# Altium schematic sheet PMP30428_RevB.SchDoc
size 431 x 279 mm; Date: Not shown in title block; ApprovedBy: Not shown in title block; CheckedBy: Not shown in title block; Author: Not shown in title block; CompanyName: Not shown in title block; Engineer: Not shown in title block; Organization: Not shown in title block; Address1: Not shown in title block; Address2: Not shown in title block; Address3: Not shown in title block; Address4: Not shown in title block; DocumentNumber: 1; Revision: Use project parameter SCH_Rev; SheetNumber: 1; SheetTotal: 1; PageSetup: Record=PageOptions¦CenterHorizontal=True¦CenterVertical=True¦PrintScale=1.00¦XCorrection=1.00¦YCorrection=1.00¦PrintKind=0¦BorderSize=5000000¦LeftOffset=0¦BottomOffset=0¦Orientation=2¦PaperLength=1000¦PaperWidth=1000¦Scale=100¦PaperSource=15¦PrintQuality=600¦MediaType=1¦DitherType=10¦PaperKind=Letter¦PrintScaleMode=1
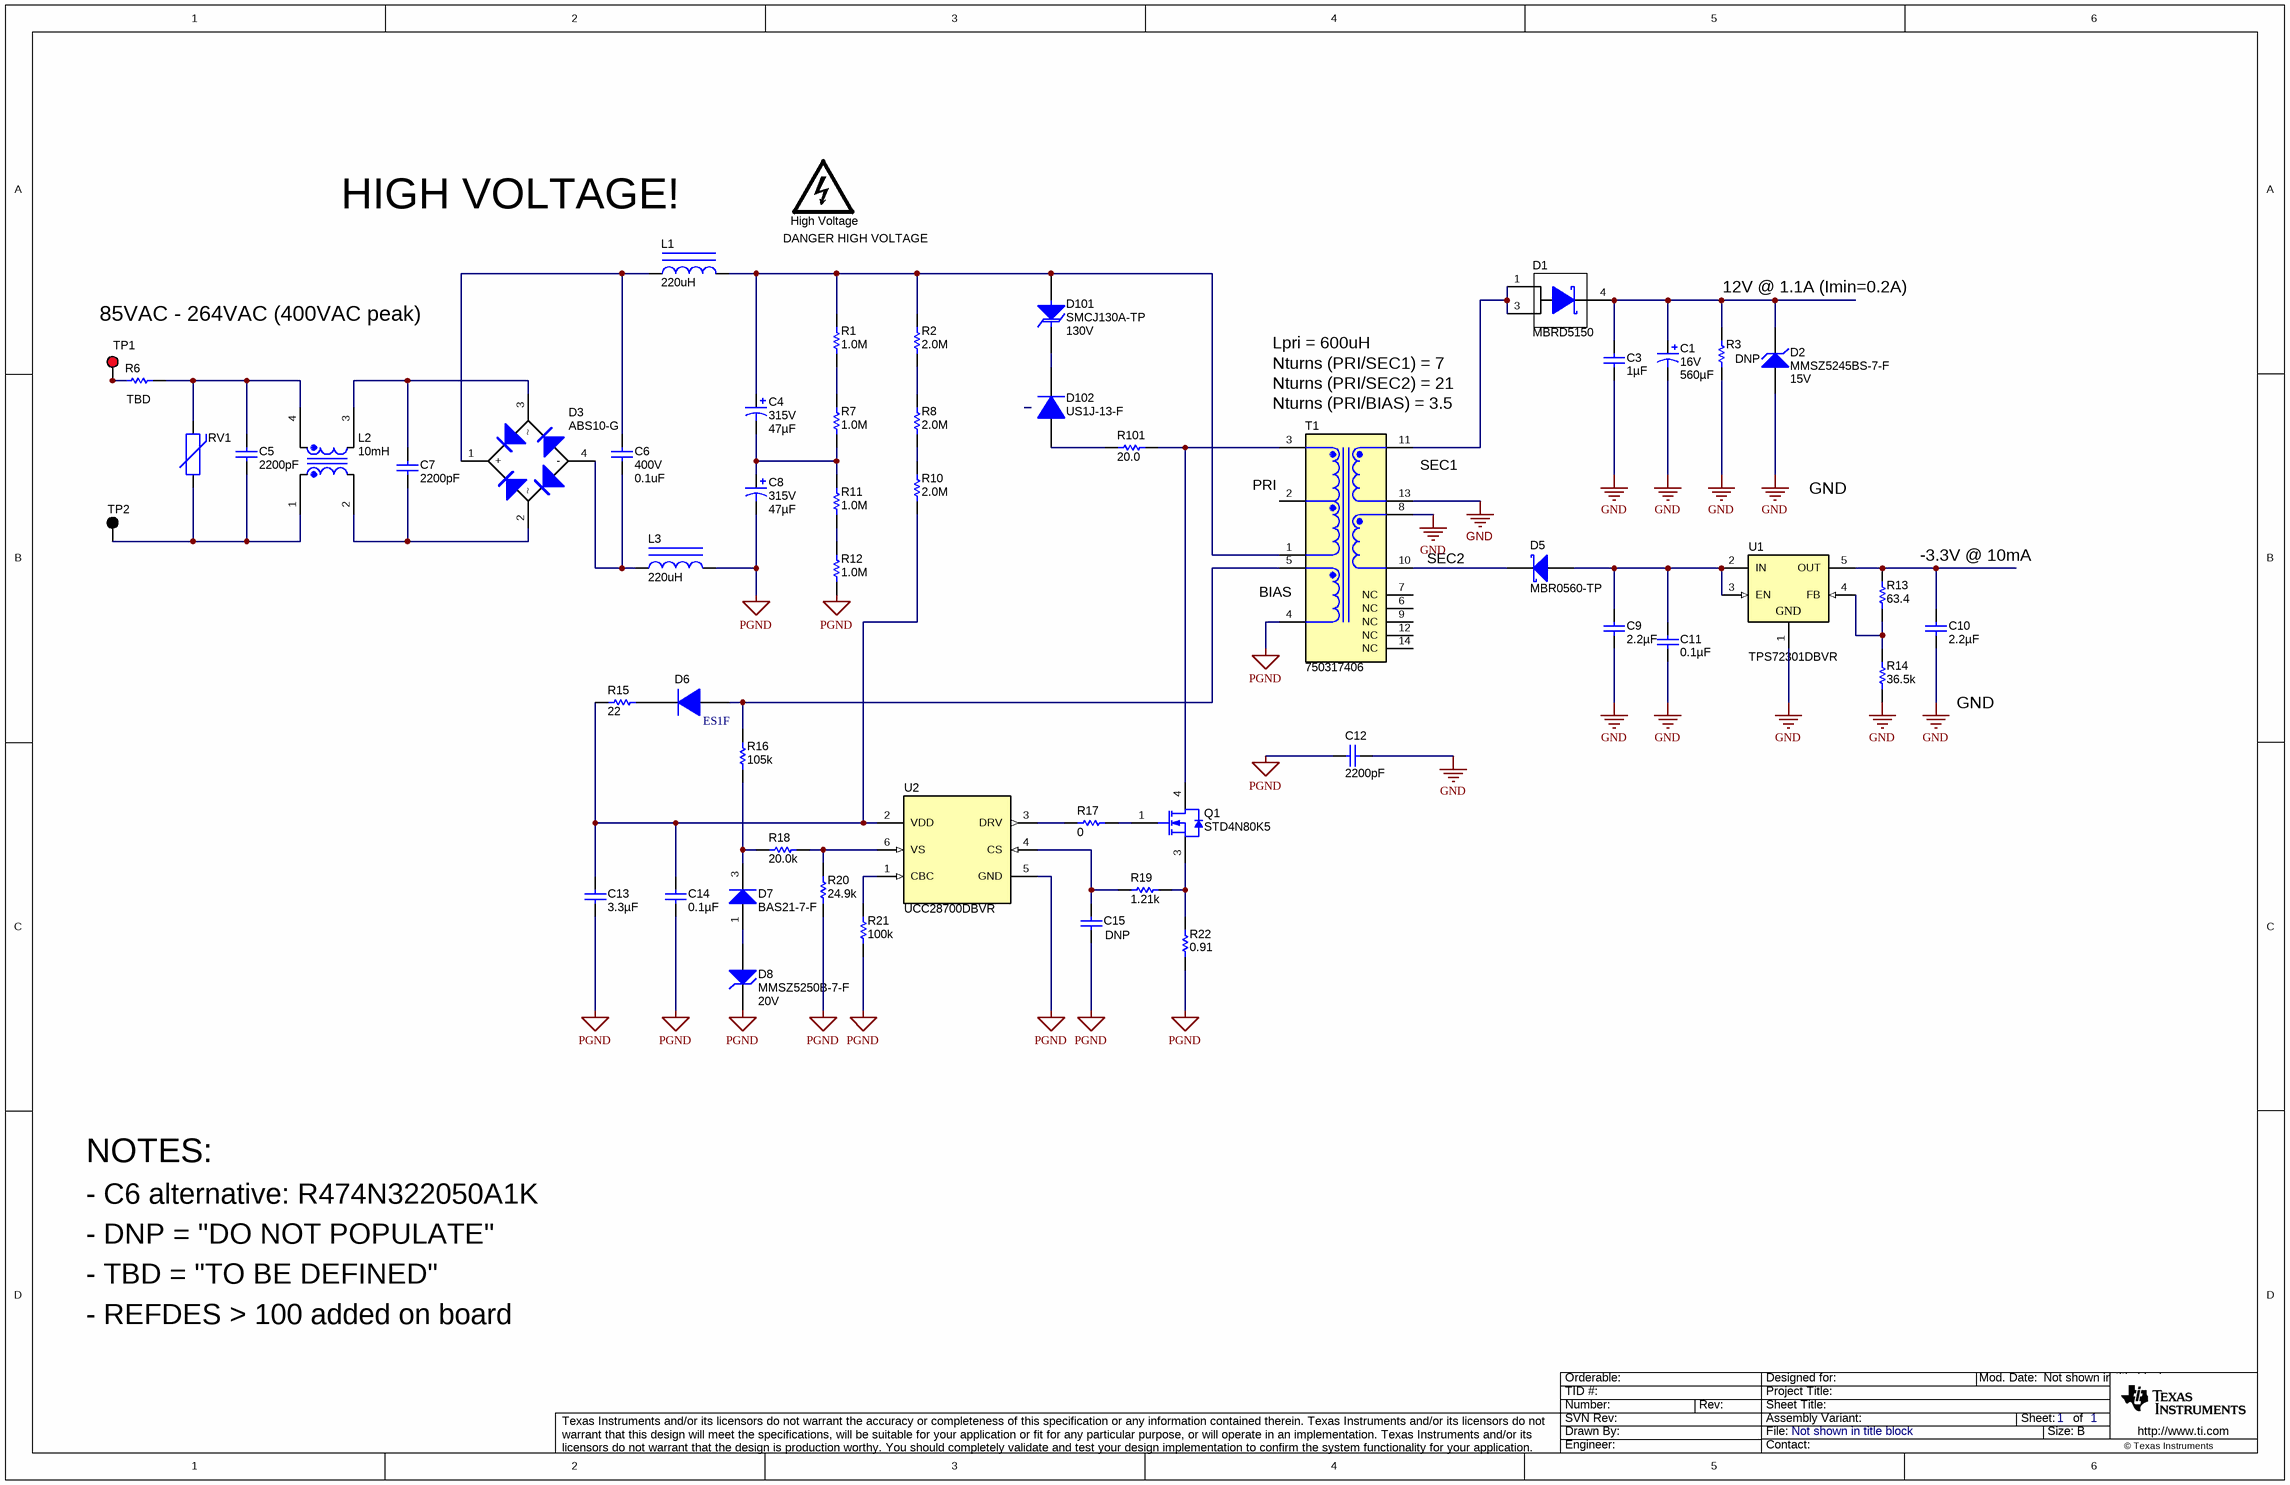
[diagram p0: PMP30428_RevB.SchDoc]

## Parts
C1  VDC_V: 16V  ValueDisplayed: 560µF  [Panasonic_SMT_800x1190]  (hidden comment: 16SVF560M)
C3  ValueDisplayed: 1µF  [0805_HV]  (hidden comment: C0805C105K4RACTU)
C4  VDC_V: 315V  ValueDisplayed: 47µF  [VZ_1600x2500]  (hidden comment: UVZ2F470MHD)
C5  ValueDisplayed: 2200pF  [VY2_900x500_5]  (hidden comment: VY2222M35Y5UG6TV5)
C6  VDC_V: 400V  ValueDisplayed: 0.1uF  [ECQE_F_1200x630x1200]  (hidden comment: ECQ-E4104JF)
C7  ValueDisplayed: 2200pF  [VY2_900x500_5]  (hidden comment: VY2222M35Y5UG6TV5)
C8  VDC_V: 315V  ValueDisplayed: 47µF  [VZ_1600x2500]  (hidden comment: UVZ2F470MHD)
C9  ValueDisplayed: 2.2µF  [0805_HV]  (hidden comment: C0805C225K8RACTU)
C10  ValueDisplayed: 2.2µF  [0805_HV]  (hidden comment: C0805C225K8RACTU)
C11  ValueDisplayed: 0.1µF  [0805_HV]  (hidden comment: GRM219R71C104KA01D)
C12  ValueDisplayed: 2200pF  [CD45_900x600x1300]  (hidden comment: CD45-E2GA222M-NKA)
C13  ValueDisplayed: 3.3µF  [1206_190]  (hidden comment: C3216X7R1H335K160AC)
C14  ValueDisplayed: 0.1µF  [0603]  (hidden comment: GRM188R71H104KA93D)
C15  value DNP  [0603]  (hidden comment: Used in BOM report)
D1  MBRD5150  [DPAK]
D2  MMSZ5245BS-7-F  value 15V  [SOD-323]
D3  ABS10-G  [ABS]
D5  MBR0560-TP  [SOD-123]
D6  ES1F  [SMA]
D7  BAS21-7-F  [SOT-23]
D8  MMSZ5250B-7-F  value 20V  [SOD-123]
D101  SMCJ130A-TP  value 130V  [SMC]
D102  US1J-13-F  [SMA]
High_Voltage  DANGER HIGH VOLTAGE  [IEC_HighVoltage_Small]  (no BOM)
L1  ValueDisplayed: 220uH  [WE-TI_5075]  (hidden comment: 7447462221)
L2  value 10mH  [Wurth_WE-TFC_UT]  (hidden comment: 744862100)
L3  ValueDisplayed: 220uH  [WE-TI_5075]  (hidden comment: 7447462221)
Q1  STD4N80K5  [DPAK]
R1  ValueDisplayed: 1.0M  [0805_HV]  (hidden comment: CRCW08051M00JNEA)
R2  ValueDisplayed: 2.0M  [0805_HV]  (hidden comment: CRCW08052M00JNEA)
R3  value DNP  [0805]  (hidden comment: Used in BOM report)
R6  TBD  [1206]
R7  ValueDisplayed: 1.0M  [0805_HV]  (hidden comment: CRCW08051M00JNEA)
R8  ValueDisplayed: 2.0M  [0805_HV]  (hidden comment: CRCW08052M00JNEA)
R10  ValueDisplayed: 2.0M  [0805_HV]  (hidden comment: CRCW08052M00JNEA)
R11  ValueDisplayed: 1.0M  [0805_HV]  (hidden comment: CRCW08051M00JNEA)
R12  ValueDisplayed: 1.0M  [0805_HV]  (hidden comment: CRCW08051M00JNEA)
R13  ValueDisplayed: 63.4  [0603]  (hidden comment: CRCW060363R4FKEA)
R14  ValueDisplayed: 36.5k  [0603]  (hidden comment: CRCW060336K5FKEA)
R15  ValueDisplayed: 22  [0805_HV]  (hidden comment: CRCW080522R0JNEA)
R16  ValueDisplayed: 105k  [0603]  (hidden comment: CRCW0603105KFKEA)
R17  ValueDisplayed: 0  [0805_HV]  (hidden comment: CRCW08050000Z0EA)
R18  ValueDisplayed: 20.0k  [0603]  (hidden comment: CRCW060320K0FKEA)
R19  ValueDisplayed: 1.21k  [0603]  (hidden comment: CRCW06031K21FKEA)
R20  ValueDisplayed: 24.9k  [0603]  (hidden comment: CRCW060324K9FKEA)
R21  ValueDisplayed: 100k  [0603]  (hidden comment: CRCW0603100KFKEA)
R22  ValueDisplayed: 0.91  [0805_HV]  (hidden comment: ERJ-6RQFR91V)
R101  ValueDisplayed: 20.0  [2010]  (hidden comment: CRCW201020R0FKEF)
RV1  B72214S0421K331  [TDK_B72214S0421]  (value not drawn)
T1  750317406  [Wurth_750317406]
TP1  5000  [Keystone5000]  (value not drawn)
TP2  5001  [Keystone5001]  (value not drawn)
U1  TPS72301DBVR  [DBV0005A_N]
U2  UCC28700DBVR  [DBV0006A_N]

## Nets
GND: C1.2(-) C3.2 C9.2 C10.2 C11.2 C12.1 D2.2(A) R3.1 R14.1 T1.8 T1.13 U1.1(GND)
PGND: C8.2(-) C12.2 C13.2 C14.2 C15.2 D8.1(K) L3.2 R12.1 R20.1 R21.1 R22.1 T1.4 U2.5(GND)
NetC1_1: C1.1(+) C3.1 D1.4(K) D2.1(K) R3.2
NetC4_1: C4.1(+) D101.2(A) L1.2 R1.2 R2.2 T1.1
NetC4_2: C4.2(-) C8.1(+) R7.1 R11.2
NetC5_1: C5.1 L2.4 R6.1 RV1.2
NetC5_2: C5.2 L2.1 RV1.1 TP2.1
NetC6_1: C6.1 D3.1(+) L1.1
NetC6_2: C6.2 D3.4(-) L3.1
NetC7_1: C7.1 D3.3 L2.3
NetC7_2: C7.2 D3.2 L2.2
NetC9_1: C9.1 C11.1 D5.2(A) U1.2(IN) U1.3(EN)
NetC10_1: C10.1 R13.2 U1.5(OUT)
NetC13_1: C13.1 C14.1 R10.1 R15.1 U2.2(VDD)
NetC15_1: C15.1 R19.1 U2.4(CS)
NetD1_1: D1.1(A) D1.3(A) T1.11
NetD5_1: D5.1(K) T1.10
NetD6_1: D6.1(K) R15.2
NetD6_2: D6.2(A) R16.2 T1.5
NetD7_1: D7.1(A) D8.2(A)
NetD7_3: D7.3(K) R16.1 R18.1
NetD101_1: D101.1(K) D102.1(K)
NetD102_2: D102.2(A) R101.1
NetQ1_1: Q1.1(G) R17.2
NetQ1_3: Q1.3(S) R19.2 R22.2
NetQ1_4: Q1.4(D) R101.2 T1.3
NetR1_1: R1.1 R7.2
NetR2_1: R2.1 R8.2
NetR6_2: R6.2 TP1.1
NetR8_1: R8.1 R10.2
NetR11_1: R11.1 R12.2
NetR13_1: R13.1 R14.2 U1.4(FB)
NetR17_1: R17.1 U2.3(DRV)
NetR18_2: R18.2 R20.2 U2.6(VS)
NetR21_2: R21.2 U2.1(CBC)

Not connected (* = marked no-connect by the designer): T1 2 6(NC) 7(NC) 9(NC) 12(NC) 14(NC)

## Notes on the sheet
- HIGH VOLTAGE!
- 12V @ 1.1A (Imin=0.2A)
- 85VAC - 264VAC (400VAC peak)
- Lpri = 600uH
- Nturns (PRI/SEC1) = 7
- Nturns (PRI/SEC2) = 21
- (near T1) Nturns (PRI/BIAS) = 3.5
- (near T1) PRI
- (near T1) SEC1
- GND
- (near T1) SEC2
- -3.3V @ 10mA
- (near T1) BIAS
- NOTES:
- - C6 alternative: R474N322050A1K
- - DNP = "DO NOT POPULATE"
- - TBD = "TO BE DEFINED"
- - REFDES > 100 added on board

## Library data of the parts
C1 = CMP-0081113-1: CAP, Aluminum Polymer, 560 µF, 16 V,+/- 20%, 0.014 ohm, 8x11.9 SMD; Manufacturer: Panasonic; TaMin_C: -55°C; ESR_ohm: 0.014; Polarized: Y; SizeAreaWB_mm2: 106.09; Value: 560uF; TaMax_C: 125°C; SizeZ_mm: 12; SizeX_mm: 8.3; Cap_Case: 0.8x11.9mm; SizeArea_mm2: 68.89; CompType: Capacitor; AEC Qualified: N; IRMS_A: 1.56A; AEC Category: Q200
C3 = C0805C105K4RACTU: CAP, CERM, 1 µF, 16 V,+/- 10%, X7R, 0805; Manufacturer: Kemet; Polarized: N; CompType: Capacitor; Value: 1uF; U/M: EA; Cap_F: 0.000001; Tolerance_%: 10; ESR_ohm: 0.015; Value1: 0.015 ohm; VDC_V: 16; Value2: 16V; IRMS_A: 8.19; TaMin_C: -55; TaMax_C: 125; Cap_Case: 0805; SizeArea_mm2: 2.5; SizeAreaWB_mm2: 6.75; SizeX_mm: 2; SizeY_mm: 1.25; SizeZ_mm: 1.45; AEC Category: Q200; Green_Lifecycle: Active; Green_REACh: Passed
C4 C8 = CMP-0081190-1: CAP, AL, 47 µF, 315 V, +/- 20%, TH; Manufacturer: Nichicon; TaMin_C: -40°C; Polarized: Y; SizeAreaWB_mm2: 324; U/M: EA; Value: 47uF; TaMax_C: 105°C; SizeZ_mm: 27; SizeX_mm: 16; Cap_Case: 16x25mm; SizeArea_mm2: 256; CompType: Capacitor; AEC Qualified: N; AEC Category: Q200
C5 = CMP-0080613-1: CAP, CERM, 2200 pF, X1 440 VAC/Y2 300 VAC, +/- 20%, Y5U, Body9x5mm; Manufacturer: Vishay-Bccomponents; TaMin_C: -40°C; Polarized: N; AC_Safety: X1Y2; SizeAreaWB_mm2: 77; U/M: EA; Value: 2200pF; TaMax_C: 125°C; VAC_Y: 300V; VAC_X: 440V; SizeZ_mm: 13; SizeX_mm: 9; SizeY_mm: 5; Cap_Case: 9x5mm; SizeArea_mm2: 45; CompType: Capacitor; Cap_F: 2.2nF; AEC Category: Q200
C6 = CMP-0064980-3: CAP, Film, 0.1 uF, 400 V,+/- 5%, TH; Manufacturer: Panasonic; TaMin_C: -40°C; Polarized: N; SizeAreaWB_mm2: 116.2; Value1: Unknown; Value: 0.1uF; TaMax_C: 105°C; SizeZ_mm: 12; SizeY_mm: 6.3; Cap_Case: 12x6.3x12mm; SizeArea_mm2: 75.6; CompType: Capacitor; Cap_F: 100nF; AEC Category: Q200
C7 = CMP-0080613-1: CAP, CERM, 2200 pF, X1 440 VAC/Y2 300 VAC, +/- 20%, Y5U, Body9x5mm; Manufacturer: Vishay-Bccomponents; TaMin_C: -40°C; Polarized: N; AC_Safety: X1Y2; SizeAreaWB_mm2: 77; U/M: EA; Value: 2200pF; TaMax_C: 125°C; VAC_Y: 300V; VAC_X: 440V; SizeZ_mm: 13; SizeX_mm: 9; SizeY_mm: 5; Cap_Case: 9x5mm; SizeArea_mm2: 45; Cap_F: 2.2nF; AEC Category: Q200
C9 C10 = C0805C225K8RACTU: CAP, CERM, 2.2 µF, 10 V,+/- 10%, X7R, 0805; Manufacturer: Kemet; Polarized: N; CompType: Capacitor; Value: 2.2uF; U/M: EA; Cap_F: 0.0000022; Tolerance_%: 10; ESR_ohm: 0.008; Value1: 0.008 ohm; Value2: 10V; IRMS_A: 15.55; TaMin_C: -55; TaMax_C: 125; Cap_Case: 0805; SizeArea_mm2: 2.5; SizeAreaWB_mm2: 6.75; SizeX_mm: 2; SizeY_mm: 1.25; SizeZ_mm: 1.45; AEC Category: Q200; Green_Lifecycle: Active; Green_REACh: Passed
C11 = GRM219R71C104KA01D: CAP, CERM, 0.1 µF, 16 V,+/- 10%, X7R, 0805; Manufacturer: MuRata; Polarized: N; CompType: Capacitor; Value: 0.1uF; U/M: EA; Cap_F: 0.0000001; Tolerance_%: 10; VDC_V: 16; Value2: 16V; TaMin_C: -55; TaMax_C: 125; Cap_Case: 0805; SizeArea_mm2: 2.5; SizeAreaWB_mm2: 6.75; SizeX_mm: 2; SizeY_mm: 1.25; SizeZ_mm: 1.45; AEC Category: Q200; Green_Lifecycle: Active; Green_REACh: Passed
C12 = CD45-E2GA222M-NKA: CAP, CERM, 2200 pF, X1 440 VAC/Y1 400 VAC, +/- 20%, E, D9xT6mm; Manufacturer: TDK; Polarized: N; CompType: Capacitor; Value: 2200pF; U/M: EA; Cap_F: 0.0000000022; Tolerance_%: 20; TaMin_C: -25; TaMax_C: 125; Cap_Case: 9x6x13mm; SizeArea_mm2: 63.9; SizeAreaWB_mm2: 101.2; SizeX_mm: 10.65; SizeY_mm: 6; SizeZ_mm: 13; AEC Category: Q200; Green_Lifecycle: Not Set; Green_REACh: Incomplete; AC_Safety: X1Y1; VAC_X: 440; VAC_Y: 400
C13 = C3216X7R1H335K160AC: CAP, CERM, 3.3 µF, 50 V,+/- 10%, X7R, 1206; Manufacturer: TDK; Polarized: N; CompType: Capacitor; Value: 3.3uF; U/M: EA; Cap_F: 0.0000033; Tolerance_%: 10; VDC_V: 50; Value2: 50V; TaMin_C: -55; TaMax_C: 125; Cap_Case: 1206; SizeArea_mm2: 5.12; SizeAreaWB_mm2: 10.92; SizeX_mm: 3.2; SizeY_mm: 1.6; SizeZ_mm: 1.9; AEC Category: Q200; Green_Lifecycle: Active; Green_REACh: Passed
C14 = GRM188R71H104KA93D: CAP, CERM, 0.1 µF, 50 V,+/- 10%, X7R, 0603; Manufacturer: MuRata; Polarized: N; CompType: Capacitor; Value: 0.1uF; U/M: EA; Cap_F: 0.0000001; Tolerance_%: 10; VDC_V: 50; Value2: 50V; TaMin_C: -55; TaMax_C: 125; SizeArea_mm2: 1.28; SizeAreaWB_mm2: 4.68; SizeX_mm: 1.6; SizeY_mm: 0.8; SizeZ_mm: 1; AEC Category: Q200; Green_Lifecycle: Active; Green_REACh: Passed
C15 = Capacitor: CAP, CERM, xxxF, xxV, [TempCo], xx%, [PackageReference]; Polarized: N; U/M: EA
D1 = MBRD360T4G: Diode, Schottky, 150V, DPAK; Manufacturer: ON Semiconductor; U/M: EA; Vf_V: 0.6; Value2: 0.6V; Io_A: 3; Vr_V: 60; TJmax_C: 150; RJC_CperW: 6; SizeAreaWB_mm2: 101.7114; SizeArea_mm2: 64.8114; SizeX_mm: 9.91; SizeY_mm: 6.54; SizeZ_mm: 2.29; AEC Category: Q101; Green_Lifecycle: Not Set; Green_REACh: Incomplete; Speed: Fast Recovery =< 500ns, > 200mA (Io); Capacitance @ Vr, F: 150pF @ 5V, 1MHz
D2 = MMSZ5245BS-7-F: Diode, Zener, 15 V, 200 mW, SOD-323; Manufacturer: Diodes Inc.; SymbolCreator: a0412235; U/M: EA; Power_W: 0.2; Vz_V: 15; Value1: 0.2W; RJA_CperW: 350; SizeAreaWB_mm2: 8.695; SizeArea_mm2: 3.645; SizeX_mm: 2.7; SizeY_mm: 1.35; SizeZ_mm: 1; AEC Category: Q101
D3 = ABS10-G: Diode, Switching-Bridge, 1000 V, 1 A, 6.2x5.0mm; Manufacturer: Comchip Technology; U/M: EA; Vf_V: 1.1; Value: 1000V; Value1: 1A; Value2: 1.1V; Io_A: 1; Vr_V: 1000; TJmax_C: 150; RJC_CperW: 12; SizeAreaWB_mm2: 57.4; SizeArea_mm2: 31; SizeX_mm: 6.2; SizeY_mm: 5; SizeZ_mm: 1.5; AEC Category: Q101; AEC Qualified: N
D5 = MBR0560-TP: Diode, Schottky, 60 V, 3 A, SOD-123; Manufacturer: Micro Commercial Components; U/M: EA; Vf_V: 0.45; Value: 60V; Value1: 3A; Value2: 0.45V; Io_A: 3; Vr_V: 60; TJmax_C: 150; SizeAreaWB_mm2: 13.095; SizeArea_mm2: 6.545; SizeX_mm: 3.85; SizeY_mm: 1.7; SizeZ_mm: 1.35; AEC Category: Q101; Green_Lifecycle: Not Set; Green_REACh: Incomplete
D6 = ES1G-13-F: Diode, Superfast Rectifier, 400 V, 1 A, SMA; Manufacturer: Diodes Inc.; U/M: EA; Vf_V: 1.25; Value: 300V; Value1: 1A; Value2: 1.25V; Io_A: 1; Vr_V: 300; TJmax_C: 150; RJC_CperW: 25; SizeAreaWB_mm2: 37.3428; SizeArea_mm2: 16.3228; SizeX_mm: 5.59; SizeY_mm: 2.92; SizeZ_mm: 2.87; AEC Category: Q101; Green_Lifecycle: Active; Green_REACh: Passed; Element Configuration: Single; Forward Voltage: 1.3V; Reverse Recovery Time: 35ns; Peak Non-Repetitive Surge Current: 30A; Peak Reverse Current: 5uA
D7 = BAS21-7-F: Diode, Switching, 200 V, 0.2 A, SOT-23; Manufacturer: Diodes Inc.; U/M: EA; Vf_V: 1.25; Value: 200V; Value1: 0.2A; Value2: 1.25V; Io_A: 0.2; Vr_V: 200; TJmax_C: 150; SizeAreaWB_mm2: 14; SizeArea_mm2: 7.5; SizeX_mm: 2.5; SizeY_mm: 3; SizeZ_mm: 1.1; AEC Category: Q101; Green_Lifecycle: Active; Green_REACh: Passed
D8 = MMSZ5250B-7-F: Diode, Zener, 20 V, 500 mW, SOD-123; Manufacturer: Diodes Inc.; SymbolCreator: a0412235; U/M: EA; Power_W: 0.5; Vz_V: 20; Value1: 0.5W; RJA_CperW: 350; SizeAreaWB_mm2: 13.095; SizeArea_mm2: 6.545; SizeX_mm: 3.85; SizeY_mm: 1.7; SizeZ_mm: 1.35; AEC Category: Q101
D101 = SMCJ120A-TP: Diode, TVS, Uni, 130 V, SMC; Manufacturer: Micro Commercial Components; U/M: EA; Vr_V: 130; Value1: W; SizeAreaWB_mm2: 83.2686; SizeArea_mm2: 50.5686; SizeX_mm: 8.13; SizeY_mm: 6.22; SizeZ_mm: 2.6; AEC Category: Q101; AEC Qualified: N
D102 = US1J-13-F: Diode, Ultrafast, 600 V, 1 A, SMA; Manufacturer: Diodes Inc.; U/M: EA; Vf_V: 1.7; Value: 600V; Value1: 1A; Value2: 1.7V; Io_A: 1; Vr_V: 600; TJmax_C: 150; SizeAreaWB_mm2: 37.3428; SizeArea_mm2: 16.3228; SizeX_mm: 5.59; SizeY_mm: 2.92; SizeZ_mm: 2.87; AEC Category: Q101; Green_Lifecycle: Active; Green_REACh: Passed
High_Voltage = IEC_HighVoltage: IEC 61010-1 High Voltage Warning; SymbolCreator: a0412235
L1 L3 = CMP-0064740-2: Inductor, Unshielded Drum Core, Ferrite, 220 uH, 0.5 A, 0.96 ohm, TH; Manufacturer: Wurth Elektronik; Isat: 0.5A @ 10% inductance drop; Irms: 0.5A @ 40C rise; Green_Lifecycle: Active; SizeAreaWB_mm2: 64; DCR_ohm: 9.6d; Green_REACh: Passed; Value: 220uH; Imax_A: 5dA; SizeZ_mm: 8.5; SizeX_mm: 6; Value2: 0.5A; SizeArea_mm2: 36; Ind_H: 220µH; AEC Category: Q200
L2 = CMP-0080644-1: Coupled inductor, 10 mH, 1.65 ohm, TH; Manufacturer: Wurth Elektronik; SizeAreaWB_mm2: 247; DCR_ohm: 1.65; SizeZ_mm: 17; SizeY_mm: 11; SizeArea_mm2: 187; AEC Qualified: N; AEC Category: Q200
Q1 = STD3NK80ZT4: MOSFET, N-CH, 800 V, DPAK; Manufacturer: STMicroelectronics; Alternate Manufacturer: None; U/M: EA; ChType: N; Value: 800V; VdsMax_V: 800; Value1: ? ohm; Value2: 19 nC; QgTyp_nC: 19; Vgs_V: 30; IdsMax_A: 2.5; SizeAreaWB_mm2: 101.7114; SizeArea_mm2: 64.8114; SizeX_mm: 9.91; SizeY_mm: 6.54; SizeZ_mm: 2.29; AEC Category: Q101; Green_Lifecycle: Active; Green_REACh: Passed; Rds On Max: 2.5R; Input Capacitance: 175pF; Rise Time: 15ns; Continuous Drain Current (ID): 3A; Max Power Dissipation: 60W; Number of Channels: 1; Drain to Source Resistance: 2.1R; Gate to Source Voltage (Vgs): 30V; Fall Time: 21ns; Element Configuration: Single
R1 R7 R11 R12 = CRCW08051M00JNEA: RES, 1.0 M, 5%, 0.125 W, 0805; Manufacturer: Vishay-Dale; CompType: Resistor; Value: 1.0Meg; Res_ohm: 1000000; Value_Code: 1M00; Tolerance_%: 5; Power_W: 0.125; Value2: 0.125W; VDC_V: 150; TempCo: 200 ppm/C; SizeArea_mm2: 2.5; SizeX_mm: 2; SizeY_mm: 1.25; SizeZ_mm: 1.45; EIA_Code: E24; U/M: EA; AEC Category: Q200
R2 R8 R10 = CRCW08052M00JNEA: RES, 2.0 M, 5%, 0.125 W, 0805; Manufacturer: Vishay-Dale; CompType: Resistor; Value: 2.0Meg; Res_ohm: 2000000; Value_Code: 2M00; Tolerance_%: 5; Power_W: 0.125; Value2: 0.125W; VDC_V: 150; TempCo: 200 ppm/C; SizeArea_mm2: 2.5; SizeX_mm: 2; SizeY_mm: 1.25; SizeZ_mm: 1.45; EIA_Code: E24; U/M: EA; AEC Category: Q200
R3 = Resistor: RES, xxx ohm, x%, xW, [PackageReference]; U/M: EA
R6 = Resistor: RES, xxx ohm, x%, xW, [PackageReference]; Manufacturer: Used in BOM report; U/M: EA
R13 = CRCW060363R4FKEA: RES, 63.4, 1%, 0.1 W, 0603; Manufacturer: Vishay-Dale; CompType: Resistor; Value: 63.4; Value_Code: 63R4; Tolerance_%: 1; Power_W: 0.1; Value2: 0.1W; VDC_V: 75; TempCo: 100 ppm/C; SizeArea_mm2: 1.28; SizeX_mm: 1.6; SizeY_mm: 0.8; EIA_Code: E96; U/M: EA; AEC Category: Q200
R14 = CRCW060336K5FKEA: RES, 36.5 k, 1%, 0.1 W, 0603; Manufacturer: Vishay-Dale; CompType: Resistor; Value: 36.5k; Res_ohm: 36500; Value_Code: 36k5; Tolerance_%: 1; Power_W: 0.1; Value2: 0.1W; VDC_V: 75; TempCo: 100 ppm/C; SizeArea_mm2: 1.28; SizeX_mm: 1.6; SizeY_mm: 0.8; EIA_Code: E96; U/M: EA; AEC Category: Q200; Green_Lifecycle: Active; Green_REACh: Passed
R15 = CRCW080522R0JNEA: RES, 22, 5%, 0.125 W, 0805; Manufacturer: Vishay-Dale; CompType: Resistor; Value: 22; Value_Code: 22R0; Tolerance_%: 5; Power_W: 0.125; Value2: 0.125W; VDC_V: 150; TempCo: 200 ppm/C; SizeArea_mm2: 2.5; SizeX_mm: 2; SizeY_mm: 1.25; SizeZ_mm: 1.45; EIA_Code: E24; U/M: EA; AEC Category: Q200; Green_Lifecycle: Active; Green_REACh: Passed
R16 = CRCW0603105KFKEA: RES, 105 k, 1%, 0.1 W, 0603; Manufacturer: Vishay-Dale; CompType: Resistor; Value: 105k; Res_ohm: 105000; Tolerance_%: 1; Power_W: 0.1; Value2: 0.1W; VDC_V: 75; TempCo: 100 ppm/C; SizeArea_mm2: 1.28; SizeX_mm: 1.6; SizeY_mm: 0.8; EIA_Code: E96; U/M: EA; AEC Category: Q200; Green_Lifecycle: Active; Green_REACh: Passed
R17 = CRCW08050000Z0EA: RES, 0, 5%, 0.125 W, 0805; Manufacturer: Vishay-Dale; CompType: Resistor; Value: 0; Value_Code: 0000; Tolerance_%: 5; Power_W: 0.125; Value2: 0.125W; VDC_V: 150; TempCo: 200 ppm/C; SizeArea_mm2: 2.5; SizeX_mm: 2; SizeY_mm: 1.25; SizeZ_mm: 1.45; EIA_Code: E24; U/M: EA; AEC Category: Q200; Green_Lifecycle: Active; Green_REACh: Passed
R18 = CRCW060320K0FKEA: RES, 20.0 k, 1%, 0.1 W, 0603; Manufacturer: Vishay-Dale; CompType: Resistor; Value: 20.0k; Res_ohm: 20000; Value_Code: 20k0; Tolerance_%: 1; Power_W: 0.1; Value2: 0.1W; VDC_V: 75; TempCo: 100 ppm/C; SizeArea_mm2: 1.28; SizeX_mm: 1.6; SizeY_mm: 0.8; EIA_Code: E96; U/M: EA; AEC Category: Q200; Green_Lifecycle: Active; Green_REACh: Passed
R19 = CRCW06031K21FKEA: RES, 1.21 k, 1%, 0.1 W, 0603; Manufacturer: Vishay-Dale; CompType: Resistor; Value: 1.21k; Res_ohm: 1210; Value_Code: 1k21; Tolerance_%: 1; Power_W: 0.1; Value2: 0.1W; VDC_V: 75; TempCo: 100 ppm/C; SizeArea_mm2: 1.28; SizeX_mm: 1.6; SizeY_mm: 0.8; EIA_Code: E96; U/M: EA; AEC Category: Q200; Green_Lifecycle: Active; Green_REACh: Passed
R20 = CRCW060324K9FKEA: RES, 24.9 k, 1%, 0.1 W, 0603; Manufacturer: Vishay-Dale; CompType: Resistor; Value: 24.9k; Res_ohm: 24900; Value_Code: 24k9; Tolerance_%: 1; Power_W: 0.1; Value2: 0.1W; VDC_V: 75; TempCo: 100 ppm/C; SizeArea_mm2: 1.28; SizeX_mm: 1.6; SizeY_mm: 0.8; EIA_Code: E96; U/M: EA; AEC Category: Q200; Green_Lifecycle: Active; Green_REACh: Passed
R21 = CRCW0603100KFKEA: RES, 100 k, 1%, 0.1 W, 0603; Manufacturer: Vishay-Dale; CompType: Resistor; Value: 100k; Res_ohm: 100000; Tolerance_%: 1; Power_W: 0.1; Value2: 0.1W; VDC_V: 75; TempCo: 100 ppm/C; SizeArea_mm2: 1.28; SizeX_mm: 1.6; SizeY_mm: 0.8; EIA_Code: E96; U/M: EA; AEC Category: Q200; Green_Lifecycle: Active; Green_REACh: Passed
R22 = ERJ-6RQFR82V: RES, 0.91, 1%, 0.125 W, 0805 current sense; Manufacturer: Panasonic; CompType: Resistor; Value: 0.82; Value_Code: R910; Tolerance_%: 1; Power_W: 0.125; Value2: 0.125W; TempCo: 250 ppm/C; SizeArea_mm2: 2.5; SizeX_mm: 2; SizeY_mm: 1.25; SizeZ_mm: 1.45; EIA_Code: E96; U/M: EA; AEC Category: Q200; Green_Lifecycle: Not Set; Green_REACh: Incomplete
R101 = CRCW201020R0FKEF: RES, 20.0, 1%, 0.75 W, AEC-Q200 Grade 0, 2010; Manufacturer: Vishay-Dale; CompType: Resistor; Value: 20.0; Res_ohm: 20; Value_Code: 20R0; Tolerance_%: 1; Power_W: 0.75; Value2: 0.75W; VDC_V: 400; TempCo: 100 ppm/C; SizeArea_mm2: 12.5; SizeX_mm: 5; SizeY_mm: 2.5; SizeZ_mm: 1.66; EIA_Code: E96; U/M: EA; AEC Category: Q200; AEC Qualified: Y; AEC Grade: 0
RV1 = CMP-0080633-1: VARISTOR; PartNumber: S14K420; Manufacturer: TDK; SizeArea_mm2: 94.55; SizeAreaWB_mm2: 141.75; SizeY_mm: 6.1; SizeZ_mm: 19; SizeX_mm: 15.5
T1 = CMP-0080922-1: Transformer, 600 uH, TH; Manufacturer: Wurth Elektronik; SizeAreaWB_mm2: 634.5; SizeArea_mm2: 537.5; AEC Qualified: N; Ns2toNp: 0.048; Lp: 600; AEC Category: Q200; Value: 600uH; SizeZ_mm: 16; Ind_H: 600µH; SizeY_mm: 21.5; Ns1toNp: 0.143; LeakageInd_H: 12µH; Rsec2_ohm: 1.1d; Rsec1_ohm: 0.03; SizeX_mm: 25
TP1 = 5000: Test Point, Miniature, Red, TH; Manufacturer: Keystone; CompType: Test Point Loop; ContactFinish: Silver
TP2 = 5001: Test Point, Miniature, Black, TH; Manufacturer: Keystone; CompType: Test Point Loop; ContactFinish: Silver
U1 = TPS72301DBVR: Single Output LDO, 200 mA, Adjustable -10 to -1.2 V Output, -10 to -2.7 V Input, 5-pin SOT-23 (DBV), -40 to 125 degC, Green (RoHS & no Sb/Br); Manufacturer: Texas Instruments; Alternate PartNumber: Equivalent; Accuracy(%): 2; Iout(Max)(A): 0.2; Iq(Typ)(mA): 0.13; SubFamily: Single Channel LDO; Vdo(Typ)(mV): 280
U2 = UCC28700DBVR: Constant-Voltage, Constant-Current PWM With Primary-Side Regulation, DBV0006A (SOT-23-6); Alternate PartNumber: UCC28700DBVT; Manufacturer: Texas Instruments; SymbolCreator: a0799628; SizeArea_mm2: 8.12; SizeAreaWB_mm2: 14.82; SizeX_mm: 2.8; SizeY_mm: 2.9; SizeZ_mm: 1.45; CompType: IC; U/M: EA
